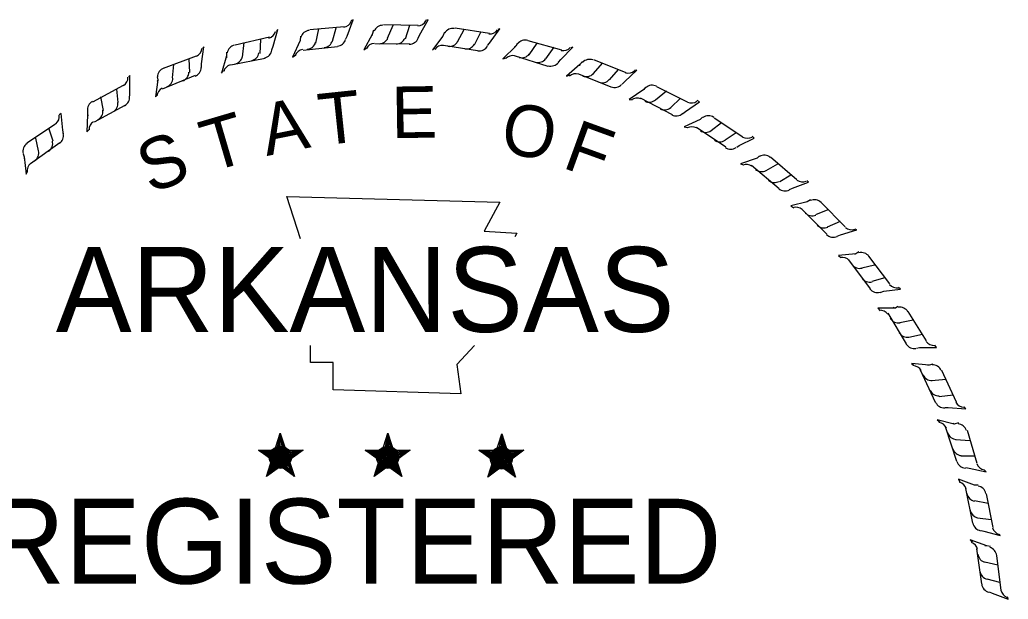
# Model space of a CAD drawing. Extents: x 0 to 42.7, y 0.9 to 22.6.
# Drawn here: x 32.193 to 33.706, y 19.762 to 20.648 of the extents above; entities that cross this region are included whole.
import ezdxf

# ---------------------------------------------------------------- set-up
doc = ezdxf.new("R2010")
doc.units = 0
doc.layers.add('R_Stamp-JLB', color=7, linetype='Continuous')

msp = doc.modelspace()

# ---------------------------------------------------------------- linework, layer by layer
at = {"layer": 'R_Stamp-JLB'}
for p, q in [((32.6944, 20.6231), (32.7037, 20.6484)), ((32.7037, 20.6484), (32.7, 20.6465)), ((32.805, 20.6249), (32.8181, 20.6484)), ((32.8181, 20.6484), (32.8144, 20.6474)), ((32.5809, 20.6081), (32.5884, 20.6334)), ((32.5884, 20.6334), (32.5856, 20.6306)), ((32.6372, 20.6334), (32.6897, 20.6381)), ((32.6466, 20.6128), (32.6512, 20.6343)), ((32.6719, 20.6156), (32.6775, 20.6362)), ((32.7347, 20.6324), (32.7328, 20.6259)), ((32.7497, 20.6409), (32.8031, 20.6399)), ((32.7562, 20.6203), (32.7647, 20.6399)), ((32.7834, 20.6193), (32.79, 20.6399)), ((32.8594, 20.6362), (32.9119, 20.6278)), ((32.8631, 20.6146), (32.8734, 20.6334)), ((32.9119, 20.6128), (32.9278, 20.6343)), ((32.9278, 20.6343), (32.925, 20.6334)), ((32.5228, 20.6099), (32.5753, 20.6221)), ((32.5612, 20.5968), (32.5622, 20.6184)), ((32.6231, 20.6231), (32.6222, 20.6165)), ((32.6925, 20.6193), (32.6944, 20.6231)), ((32.7328, 20.6259), (32.7197, 20.6024)), ((32.7328, 20.6259), (32.7319, 20.624)), ((32.8031, 20.6203), (32.805, 20.6249)), ((32.8406, 20.6231), (32.8247, 20.6024)), ((32.8406, 20.6231), (32.8397, 20.6221)), ((32.8434, 20.6296), (32.8406, 20.6231)), ((32.8894, 20.6099), (32.8987, 20.6296)), ((32.4712, 20.5809), (32.475, 20.6071)), ((32.475, 20.6071), (32.4731, 20.6043)), ((32.5341, 20.5912), (32.5369, 20.6137)), ((32.5791, 20.6024), (32.5809, 20.6081)), ((32.6222, 20.6165), (32.6109, 20.5912)), ((32.6222, 20.6165), (32.6212, 20.6146)), ((32.6794, 20.6071), (32.6269, 20.6015)), ((32.7197, 20.6024), (32.7244, 20.6053)), ((32.79, 20.6109), (32.7365, 20.6118)), ((32.8247, 20.6024), (32.8284, 20.6053)), ((32.894, 20.6006), (32.8415, 20.609)), ((32.909, 20.609), (32.9119, 20.6128)), ((32.9522, 20.6081), (32.9325, 20.5884)), ((32.9522, 20.6081), (32.9503, 20.6062)), ((32.955, 20.6128), (32.9522, 20.6081)), ((32.9709, 20.6165), (33.0225, 20.6024)), ((32.9728, 20.5949), (32.985, 20.6128)), ((32.9981, 20.5884), (33.0112, 20.6062)), ((33.0215, 20.5874), (33.0394, 20.6062)), ((33.0394, 20.6062), (33.0365, 20.6053)), ((32.4131, 20.5743), (32.4637, 20.5931)), ((32.4534, 20.5678), (32.4525, 20.5884)), ((32.5097, 20.5931), (32.5022, 20.5668)), ((32.5097, 20.5987), (32.5097, 20.5931)), ((32.5097, 20.5931), (32.5097, 20.5903)), ((32.5687, 20.5893), (32.5162, 20.579)), ((32.6109, 20.5912), (32.6156, 20.5949)), ((32.9325, 20.5884), (32.9381, 20.5903)), ((33.0019, 20.5771), (32.9503, 20.5931)), ((33.0178, 20.5837), (33.0215, 20.5874)), ((33.0712, 20.5874), (33.1209, 20.5678)), ((32.4272, 20.5593), (32.4291, 20.5799)), ((32.4712, 20.5753), (32.4712, 20.5809)), ((33.0506, 20.5799), (33.03, 20.5621)), ((33.0506, 20.5799), (33.0497, 20.5781)), ((33.0544, 20.5846), (33.0506, 20.5799)), ((33.0712, 20.5659), (33.0853, 20.5818)), ((33.0956, 20.5565), (33.1097, 20.5724)), ((33.119, 20.5537), (33.1378, 20.5715)), ((33.1378, 20.5715), (33.134, 20.5706)), ((32.3616, 20.5631), (32.3597, 20.5603)), ((32.3616, 20.5368), (32.3616, 20.5631)), ((32.4047, 20.5565), (32.4009, 20.5303)), ((32.4037, 20.5612), (32.4047, 20.5565)), ((32.4047, 20.5565), (32.4037, 20.5537)), ((32.4619, 20.5631), (32.4112, 20.5424)), ((32.5022, 20.5668), (32.505, 20.5706)), ((33.03, 20.5621), (33.0356, 20.564)), ((33.0984, 20.5453), (33.0487, 20.5649)), ((32.3053, 20.5228), (32.3522, 20.5481)), ((32.3437, 20.5218), (32.3419, 20.5424)), ((33.1153, 20.5499), (33.119, 20.5537)), ((33.1481, 20.5415), (33.1256, 20.5265)), ((33.1481, 20.5415), (33.1453, 20.5396)), ((33.1509, 20.5453), (33.1481, 20.5415)), ((33.1678, 20.5462), (33.2147, 20.5228)), ((32.3212, 20.5096), (32.3175, 20.5303)), ((32.3616, 20.5321), (32.3616, 20.5368)), ((32.4009, 20.5303), (32.4037, 20.5331)), ((33.1256, 20.5265), (33.1303, 20.5256)), ((33.1922, 20.5031), (33.1434, 20.5284)), ((33.1659, 20.5256), (33.1828, 20.5396)), ((33.1894, 20.5143), (33.2044, 20.5284)), ((32.3541, 20.5171), (32.3072, 20.4918)), ((33.2119, 20.5078), (33.2334, 20.5228)), ((33.2334, 20.5228), (33.2297, 20.5246)), ((32.2566, 20.5049), (32.2537, 20.5031)), ((32.2594, 20.4796), (32.2566, 20.5049)), ((32.2969, 20.5031), (32.2959, 20.4768)), ((32.2969, 20.5087), (32.2969, 20.5031)), ((32.2969, 20.5031), (32.2978, 20.5012)), ((33.2081, 20.5049), (33.2119, 20.5078)), ((33.2381, 20.4993), (33.2344, 20.4956)), ((33.2559, 20.4984), (33.3, 20.4693)), ((32.2041, 20.4599), (32.2481, 20.489)), ((32.2444, 20.4628), (32.2378, 20.4824)), ((33.2344, 20.4956), (33.21, 20.4843)), ((33.21, 20.4843), (33.2147, 20.4834)), ((33.2737, 20.4534), (33.2287, 20.4834)), ((33.2344, 20.4956), (33.2325, 20.4946)), ((33.2512, 20.4787), (33.2672, 20.4909)), ((32.2219, 20.4478), (32.2181, 20.4674)), ((32.2603, 20.474), (32.2594, 20.4796)), ((32.2959, 20.4768), (32.2997, 20.4806)), ((33.2728, 20.4646), (33.2897, 20.4759)), ((33.2944, 20.4562), (33.3169, 20.4674)), ((33.3169, 20.4674), (33.314, 20.4703)), ((32.2547, 20.4599), (32.2097, 20.4281)), ((33.2906, 20.4534), (33.2944, 20.4562)), ((32.1984, 20.4431), (32.2003, 20.4384)), ((32.2003, 20.4384), (32.2031, 20.4121)), ((32.2003, 20.4384), (32.2003, 20.4356)), ((33.3215, 20.4365), (33.2962, 20.4281)), ((33.3215, 20.4365), (33.3187, 20.4356)), ((33.3253, 20.4403), (33.3215, 20.4365)), ((33.3422, 20.4384), (33.3825, 20.4037)), ((33.2962, 20.4281), (33.3009, 20.4262)), ((33.3553, 20.3896), (33.3131, 20.4253)), ((33.3356, 20.4178), (33.3534, 20.4281)), ((32.2031, 20.4121), (32.205, 20.4168)), ((33.3562, 20.4009), (33.3731, 20.4112)), ((33.3712, 20.3887), (33.3759, 20.3906)), ((33.3759, 20.3906), (33.4003, 20.3999)), ((33.4003, 20.3999), (33.3975, 20.4018)), ((33.3984, 20.3699), (33.3731, 20.3634)), ((33.3731, 20.3634), (33.3778, 20.3606)), ((33.3984, 20.3699), (33.3965, 20.369)), ((33.4031, 20.3728), (33.3984, 20.3699)), ((33.419, 20.369), (33.4565, 20.3315)), ((33.4284, 20.3203), (33.39, 20.3587)), ((33.4115, 20.3503), (33.4303, 20.3578)), ((33.4294, 20.3315), (33.449, 20.3399)), ((33.4444, 20.3174), (33.449, 20.3193)), ((33.449, 20.3193), (33.4744, 20.3268)), ((33.4744, 20.3268), (33.4715, 20.3278)), ((33.4725, 20.2903), (33.4462, 20.2874)), ((33.4462, 20.2874), (33.45, 20.2846)), ((33.4725, 20.2903), (33.4706, 20.2893)), ((33.4772, 20.2931), (33.4725, 20.2903)), ((33.4922, 20.2865), (33.524, 20.2443)), ((33.495, 20.2368), (33.4622, 20.2809)), ((33.4819, 20.2687), (33.5015, 20.2734)), ((33.4978, 20.2481), (33.5175, 20.2537)), ((33.5409, 20.2359), (33.5381, 20.2387)), ((33.51, 20.2312), (33.5156, 20.2331)), ((33.5156, 20.2331), (33.5409, 20.2359)), ((33.5372, 20.2096), (33.5334, 20.2068)), ((33.5334, 20.2068), (33.5062, 20.2068)), ((33.5062, 20.2068), (33.51, 20.2031)), ((33.5503, 20.1524), (33.5222, 20.1993)), ((33.5334, 20.2068), (33.5297, 20.2078)), ((33.5522, 20.2021), (33.5803, 20.1571)), ((33.54, 20.1853), (33.5606, 20.189)), ((33.554, 20.1628), (33.5747, 20.1674)), ((33.5962, 20.1468), (33.5934, 20.1506)), ((33.5653, 20.1459), (33.57, 20.1468)), ((33.57, 20.1468), (33.5962, 20.1468)), ((33.585, 20.1196), (33.5578, 20.1224)), ((33.5578, 20.1224), (33.5615, 20.1196)), ((33.585, 20.1196), (33.5822, 20.1196)), ((33.5906, 20.1215), (33.585, 20.1196)), ((33.5944, 20.0624), (33.5719, 20.1121)), ((33.6037, 20.1121), (33.6262, 20.0634)), ((33.5887, 20.0962), (33.6112, 20.0981)), ((33.6, 20.0718), (33.6215, 20.0746)), ((33.6094, 20.0549), (33.614, 20.0549)), ((33.614, 20.0549), (33.6412, 20.0531)), ((33.6412, 20.0531), (33.6384, 20.0559)), ((33.6234, 20.0296), (33.5972, 20.0362)), ((33.5972, 20.0362), (33.6019, 20.0324)), ((33.6234, 20.0296), (33.6215, 20.0306)), ((33.63, 20.0315), (33.6234, 20.0296)), ((32.5918, 20.0155), (32.5868, 19.9915)), ((32.5918, 20.0155), (32.5888, 19.9905)), ((32.5918, 20.0155), (32.5908, 19.9905)), ((32.5918, 19.9785), (32.5918, 20.0155)), ((32.5918, 20.0155), (32.5988, 19.9905)), ((32.5918, 20.0155), (32.5968, 19.9905)), ((32.5918, 20.0155), (32.5948, 19.9905)), ((32.7568, 20.0155), (32.7518, 19.9915)), ((32.7568, 20.0155), (32.7528, 19.9905)), ((32.7568, 20.0155), (32.7548, 19.9905)), ((32.7568, 19.9785), (32.7568, 20.0155)), ((32.7568, 20.0155), (32.7628, 19.9905)), ((32.7568, 20.0155), (32.7618, 19.9905)), ((32.7568, 20.0155), (32.7588, 19.9905)), ((32.9308, 20.0145), (32.9258, 19.9895)), ((32.9308, 20.0145), (32.9268, 19.9895)), ((32.9308, 20.0145), (32.9298, 19.9895)), ((32.9308, 19.9785), (32.9308, 20.0145)), ((32.9308, 20.0145), (32.9368, 19.9895)), ((32.9308, 20.0145), (32.9358, 19.9895)), ((32.9308, 20.0145), (32.9328, 19.9895)), ((33.6272, 19.9724), (33.6103, 20.024)), ((33.6431, 20.0203), (33.6581, 19.9696)), ((33.6253, 20.0062), (33.6478, 20.0043)), ((32.5588, 19.9895), (32.5918, 19.9785)), ((32.5588, 19.9895), (32.5828, 19.9875)), ((32.5588, 19.9895), (32.5828, 19.9855)), ((32.5588, 19.9895), (32.5818, 19.9835)), ((32.5588, 19.9895), (32.5818, 19.9805)), ((32.5588, 19.9895), (32.5808, 19.9785)), ((32.5588, 19.9895), (32.5808, 19.9755)), ((32.6268, 19.9895), (32.5918, 19.9785)), ((32.6268, 19.9895), (32.5958, 19.9885)), ((32.6268, 19.9895), (32.5988, 19.9855)), ((32.6268, 19.9895), (32.5988, 19.9835)), ((32.6268, 19.9895), (32.6048, 19.9815)), ((32.6268, 19.9895), (32.6068, 19.9805)), ((32.6268, 19.9895), (32.6078, 19.9785)), ((32.7218, 19.9895), (32.7568, 19.9785)), ((32.7218, 19.9895), (32.7478, 19.9875)), ((32.7218, 19.9895), (32.7478, 19.9855)), ((32.7218, 19.9895), (32.7468, 19.9835)), ((32.7218, 19.9895), (32.7458, 19.9805)), ((32.7218, 19.9895), (32.7458, 19.9785)), ((32.7218, 19.9895), (32.7458, 19.9755)), ((32.7908, 19.9895), (32.7568, 19.9785)), ((32.7908, 19.9895), (32.7608, 19.9885)), ((32.7908, 19.9895), (32.7628, 19.9855)), ((32.7908, 19.9895), (32.7628, 19.9835)), ((32.7908, 19.9895), (32.7688, 19.9815)), ((32.7908, 19.9895), (32.7708, 19.9805)), ((32.7908, 19.9895), (32.7728, 19.9785)), ((32.8958, 19.9895), (32.9308, 19.9785)), ((32.8958, 19.9895), (32.9218, 19.9865)), ((32.8958, 19.9895), (32.9218, 19.9845)), ((32.8958, 19.9895), (32.9208, 19.9825)), ((32.8958, 19.9895), (32.9198, 19.9795)), ((32.8958, 19.9895), (32.9198, 19.9775)), ((32.8958, 19.9895), (32.9198, 19.9745)), ((32.9648, 19.9895), (32.9308, 19.9785)), ((32.9648, 19.9895), (32.9348, 19.9865)), ((32.9648, 19.9895), (32.9368, 19.9845)), ((32.9648, 19.9895), (32.9368, 19.9815)), ((32.9648, 19.9895), (32.9438, 19.9805)), ((32.9648, 19.9895), (32.9448, 19.9785)), ((32.9648, 19.9895), (32.9468, 19.9785)), ((32.5708, 19.9495), (32.5918, 19.9785)), ((32.5708, 19.9495), (32.5818, 19.9775)), ((32.5708, 19.9495), (32.5838, 19.9745)), ((32.5708, 19.9495), (32.5848, 19.9735)), ((32.5708, 19.9495), (32.5888, 19.9705)), ((32.5708, 19.9495), (32.5918, 19.9705)), ((32.5708, 19.9495), (32.5928, 19.9685)), ((32.6138, 19.9495), (32.5918, 19.9785)), ((32.6138, 19.9495), (32.5918, 19.9705)), ((32.6138, 19.9495), (32.5918, 19.9675)), ((32.6138, 19.9495), (32.5958, 19.9705)), ((32.6138, 19.9495), (32.5998, 19.9785)), ((32.6138, 19.9495), (32.5998, 19.9745)), ((32.6138, 19.9495), (32.6028, 19.9785)), ((32.7358, 19.9495), (32.7568, 19.9785)), ((32.7358, 19.9495), (32.7468, 19.9775)), ((32.7358, 19.9495), (32.7478, 19.9745)), ((32.7358, 19.9495), (32.7498, 19.9735)), ((32.7358, 19.9495), (32.7528, 19.9705)), ((32.7358, 19.9495), (32.7558, 19.9705)), ((32.7358, 19.9495), (32.7578, 19.9685)), ((32.7778, 19.9495), (32.7558, 19.9705)), ((32.7778, 19.9495), (32.7558, 19.9675)), ((32.7778, 19.9495), (32.7568, 19.9785)), ((32.7778, 19.9495), (32.7598, 19.9705)), ((32.7778, 19.9495), (32.7638, 19.9785)), ((32.7778, 19.9495), (32.7638, 19.9745)), ((32.7778, 19.9495), (32.7668, 19.9785)), ((32.9098, 19.9485), (32.9308, 19.9785)), ((32.9098, 19.9485), (32.9208, 19.9755)), ((32.9098, 19.9485), (32.9218, 19.9725)), ((32.9098, 19.9485), (32.9238, 19.9715)), ((32.9098, 19.9485), (32.9298, 19.9705)), ((32.9098, 19.9485), (32.9268, 19.9695)), ((32.9098, 19.9485), (32.9308, 19.9675)), ((32.9518, 19.9485), (32.9298, 19.9705)), ((32.9518, 19.9485), (32.9298, 19.9665)), ((32.9518, 19.9485), (32.9308, 19.9785)), ((32.9518, 19.9485), (32.9338, 19.9695)), ((32.9518, 19.9485), (32.9368, 19.9725)), ((32.9518, 19.9485), (32.9378, 19.9775)), ((32.9518, 19.9485), (32.9408, 19.9775)), ((33.6337, 19.9809), (33.6544, 19.9809)), ((33.6412, 19.9631), (33.6459, 19.9621)), ((33.6459, 19.9621), (33.6722, 19.9565)), ((33.6722, 19.9565), (33.6694, 19.9593)), ((33.6544, 19.9359), (33.63, 19.9453)), ((33.63, 19.9453), (33.6319, 19.9406)), ((33.6544, 19.9359), (33.6525, 19.9368)), ((33.6515, 19.8778), (33.6412, 19.9312)), ((33.66, 19.9359), (33.6544, 19.9359)), ((33.6722, 19.9228), (33.6825, 19.8712)), ((33.6544, 19.9124), (33.675, 19.9087)), ((33.659, 19.8862), (33.6797, 19.8834)), ((33.6647, 19.8665), (33.6684, 19.8656)), ((33.6684, 19.8656), (33.6937, 19.859)), ((33.6937, 19.859), (33.6928, 19.8609)), ((33.6731, 19.8431), (33.6478, 19.8525)), ((33.6478, 19.8525), (33.6506, 19.8487)), ((33.6656, 19.785), (33.6581, 19.8384)), ((33.6731, 19.8431), (33.6703, 19.8431)), ((33.6787, 19.8421), (33.6731, 19.8431)), ((33.6703, 19.8187), (33.69, 19.814)), ((33.6881, 19.8281), (33.6947, 19.7756)), ((33.6731, 19.7925), (33.6928, 19.7878)), ((33.6769, 19.7728), (33.6815, 19.7709)), ((33.6815, 19.7709), (33.7059, 19.7615)), ((33.7059, 19.7615), (33.705, 19.7653))]:
    msp.add_line(p, q, dxfattribs=at)
for points in [[(32.6231, 20.313), (32.6021, 20.378), (32.9281, 20.369), (32.9041, 20.325), (32.9541, 20.322), (32.9511, 20.316)], [(32.8891, 20.15), (32.8621, 20.121), (32.8681, 20.076), (32.6731, 20.082), (32.6731, 20.124), (32.6381, 20.124), (32.6381, 20.15)], [(32.5918, 20.0155), (32.6138, 19.9495), (32.5588, 19.9895), (32.6268, 19.9895), (32.5708, 19.9495), (32.5918, 20.0155)], [(32.7568, 20.0155), (32.7778, 19.9495), (32.7218, 19.9895), (32.7908, 19.9895), (32.7358, 19.9495), (32.7568, 20.0155)], [(32.9308, 20.0145), (32.9518, 19.9485), (32.8958, 19.9895), (32.9648, 19.9895), (32.9098, 19.9485), (32.9308, 20.0145)]]:
    msp.add_lwpolyline(points, dxfattribs=at)
for centre, radius in [((32.5921, 19.9788), 0.017), ((32.5921, 19.9788), 0.0153), ((32.5921, 19.9788), 0.0142), ((32.5921, 19.9788), 0.0131), ((32.5921, 19.9788), 0.0114), ((32.5921, 19.9788), 0.0106), ((32.5921, 19.9788), 0.00975), ((32.5921, 19.9788), 0.00839), ((32.5921, 19.9788), 0.00735), ((32.5921, 19.9788), 0.00612), ((32.5921, 19.9788), 0.00488), ((32.5921, 19.9788), 0.00364), ((32.5921, 19.9788), 0.00292), ((32.7564, 19.9788), 0.017), ((32.7564, 19.9788), 0.0153), ((32.7564, 19.9788), 0.0142), ((32.7564, 19.9788), 0.0131), ((32.7564, 19.9788), 0.0114), ((32.7564, 19.9788), 0.0106), ((32.7564, 19.9788), 0.00975), ((32.7564, 19.9788), 0.00839), ((32.7564, 19.9788), 0.00735), ((32.7564, 19.9788), 0.00612), ((32.7564, 19.9788), 0.00488), ((32.7564, 19.9788), 0.00364), ((32.7564, 19.9788), 0.00292), ((32.9303, 19.9776), 0.017), ((32.9303, 19.9776), 0.0153), ((32.9303, 19.9776), 0.0142), ((32.9303, 19.9776), 0.0131), ((32.9303, 19.9776), 0.0114), ((32.9303, 19.9776), 0.0106), ((32.9303, 19.9776), 0.00975), ((32.9303, 19.9776), 0.00839), ((32.9303, 19.9776), 0.00735), ((32.9303, 19.9776), 0.00612), ((32.9303, 19.9776), 0.00488), ((32.5921, 19.9788), 0.00142), ((32.7564, 19.9788), 0.00142), ((32.9303, 19.9776), 0.00364), ((32.9303, 19.9776), 0.00292), ((32.9303, 19.9776), 0.00142)]:
    msp.add_circle(centre, radius, dxfattribs=at)
for centre, start, end in [((32.6376, 20.6176), 95.6641, 164.0381), ((32.6869, 20.6515), 279.9249, 338.7128), ((32.7489, 20.6254), 89.1628, 157.5368), ((32.8017, 20.6535), 273.4236, 332.2115), ((32.8562, 20.6206), 81.4231, 149.797), ((32.9123, 20.6413), 265.6839, 324.4717), ((32.5705, 20.6343), 286.2701, 345.0579), ((32.6779, 20.6224), 275.6641, 344.0381), ((32.7433, 20.6263), 269.1628, 337.5368), ((32.7693, 20.6259), 269.1628, 337.5368), ((32.7895, 20.6256), 269.1628, 337.5368), ((32.9667, 20.6026), 73.9909, 142.3649), ((32.4576, 20.606), 294.8371, 353.6249), ((32.5252, 20.5952), 102.0093, 170.3833), ((32.5648, 20.6044), 282.0093, 350.3833), ((32.6286, 20.5886), 99.9249, 158.7128), ((32.6319, 20.6179), 275.6641, 344.0381), ((32.6578, 20.6204), 275.6641, 344.0381), ((32.7366, 20.5976), 93.4236, 152.2115), ((32.8403, 20.5946), 85.6839, 144.4717), ((32.8507, 20.6223), 261.4231, 329.797), ((32.8765, 20.6183), 261.4231, 329.797), ((32.8964, 20.6153), 261.4231, 329.797), ((33.025, 20.6158), 258.2517, 317.0395), ((32.5196, 20.5949), 282.0093, 350.3833), ((32.545, 20.6002), 282.0093, 350.3833), ((32.9476, 20.5789), 78.2517, 137.0395), ((32.9615, 20.6049), 253.9909, 322.3649), ((32.9865, 20.5977), 253.9909, 322.3649), ((33.0653, 20.5732), 69.0955, 137.4695), ((32.4187, 20.5606), 110.5763, 178.9503), ((32.4564, 20.5756), 290.5763, 358.9503), ((32.5195, 20.5653), 106.2701, 165.0579), ((33.0059, 20.5921), 253.9909, 322.3649), ((32.3443, 20.5602), 301.9545, 0.7423), ((32.4131, 20.5594), 290.5763, 358.9503), ((32.4375, 20.5684), 290.5763, 358.9503), ((33.0442, 20.5512), 73.3563, 132.1441), ((33.0603, 20.5759), 249.0955, 317.4695), ((33.0846, 20.5666), 249.0955, 317.4695), ((33.1245, 20.5814), 253.3563, 312.1441), ((32.4175, 20.5302), 114.8371, 173.6249), ((33.1035, 20.5594), 249.0955, 317.4695), ((33.1611, 20.5336), 63.0708, 131.4448), ((32.3469, 20.5298), 297.6937, 6.0677), ((33.1379, 20.514), 67.3316, 126.1194), ((32.3113, 20.5103), 117.6937, 186.0677), ((32.329, 20.5204), 297.6937, 6.0677), ((33.1565, 20.5369), 243.0708, 311.4448), ((33.1797, 20.525), 243.0708, 311.4448), ((33.2209, 20.5356), 247.3316, 306.1194), ((32.2393, 20.5006), 309.1135, 7.9014), ((32.306, 20.5084), 297.6937, 6.0677), ((33.1977, 20.5159), 243.0708, 311.4448), ((33.2471, 20.4869), 56.1736, 124.5476), ((32.3139, 20.4799), 121.9545, 180.7423), ((33.2216, 20.4701), 60.4344, 119.2222), ((32.2456, 20.4709), 304.8528, 13.2267), ((33.2429, 20.4907), 236.1736, 304.5476), ((33.3067, 20.4816), 240.4344, 299.2222), ((32.2128, 20.447), 124.8528, 193.2267), ((32.2291, 20.4593), 304.8528, 13.2267), ((33.2644, 20.4761), 236.1736, 304.5476), ((33.2812, 20.4649), 236.1736, 304.5476), ((32.2077, 20.4445), 304.8528, 13.2267), ((33.3323, 20.4264), 50.1902, 118.5642), ((32.2191, 20.4172), 129.1135, 187.9014), ((33.3053, 20.4124), 54.451, 113.2388), ((33.3285, 20.4306), 230.1902, 298.5642), ((33.3484, 20.4139), 230.1902, 298.5642), ((33.391, 20.4149), 234.451, 293.2388), ((33.364, 20.401), 230.1902, 298.5642), ((33.3809, 20.3469), 49.2262, 108.0141), ((33.4091, 20.3583), 44.9655, 113.3394), ((33.4057, 20.3629), 224.9655, 293.3394), ((33.4241, 20.3444), 224.9655, 293.3394), ((33.4666, 20.3416), 229.2262, 288.0141), ((33.4384, 20.3302), 224.9655, 293.3394), ((33.4515, 20.2702), 40.9505, 99.7383), ((33.4811, 20.2775), 36.6897, 105.0637), ((33.4784, 20.2825), 216.6897, 285.0637), ((33.4939, 20.2615), 216.6897, 285.0637), ((33.5355, 20.2527), 220.9505, 279.7383), ((33.506, 20.2454), 216.6897, 285.0637), ((33.5401, 20.1939), 31.7427, 100.1166), ((33.5101, 20.1892), 36.0034, 94.7913), ((33.5379, 20.1991), 211.7427, 280.1166), ((33.5515, 20.177), 211.7427, 280.1166), ((33.5622, 20.1598), 211.7427, 280.1166), ((33.5922, 20.1645), 216.0034, 274.7913), ((33.5599, 20.1044), 29.1451, 87.9329), ((33.5903, 20.1055), 24.8843, 93.2583), ((33.5887, 20.111), 204.8843, 273.2583), ((33.5996, 20.0873), 204.8843, 273.2583), ((33.6081, 20.069), 204.8843, 273.2583), ((33.6385, 20.0701), 209.1451, 267.9329), ((33.5978, 20.0178), 22.0938, 80.8817), ((33.6281, 20.0152), 17.8331, 86.207), ((33.6272, 20.0208), 197.8331, 266.207), ((33.6351, 19.996), 197.8331, 266.207), ((33.6413, 19.9767), 197.8331, 266.207), ((33.6716, 19.9741), 202.0938, 260.8817), ((33.6275, 19.9264), 15.7912, 74.579), ((33.657, 19.9261), 191.5304, 259.9044), ((33.6573, 19.9204), 11.5304, 79.9044), ((33.6621, 19.9006), 191.5304, 259.9044), ((33.6662, 19.8808), 191.5304, 259.9044), ((33.696, 19.8748), 195.7912, 254.579), ((33.6446, 19.8348), 11.4348, 70.2227), ((33.6741, 19.8322), 187.174, 255.548), ((33.6739, 19.8266), 7.174, 75.548), ((33.6772, 19.8064), 187.174, 255.548), ((33.6798, 19.7864), 187.174, 255.548), ((33.7091, 19.7781), 191.4348, 250.2227)]:
    msp.add_arc(centre, 0.0146, start, end, dxfattribs=at)

# ---------------------------------------------------------------- texts
for s, rotation, p in [('E', 0.8323, (32.7624, 20.4671)), ('T', 6.0228, (32.6543, 20.456)), ('A', 11.2132, (32.5711, 20.4397)), ('O', 350.4515, (32.9265, 20.4457)), ('T', 16.4036, (32.4847, 20.4147)), ('F', 340.0707, (33.0215, 20.4227)), ('S', 21.594, (32.3933, 20.3813))]:
    msp.add_text(s, height=0.0789, rotation=rotation, dxfattribs=at).set_placement(p)
for s, p in [('ARKANSAS', (32.2486, 20.1706)), ('REGISTERED', (32.1371, 19.7854))]:
    msp.add_text(s, height=0.13, dxfattribs=at).set_placement(p)

doc.saveas('drawing.dxf')
